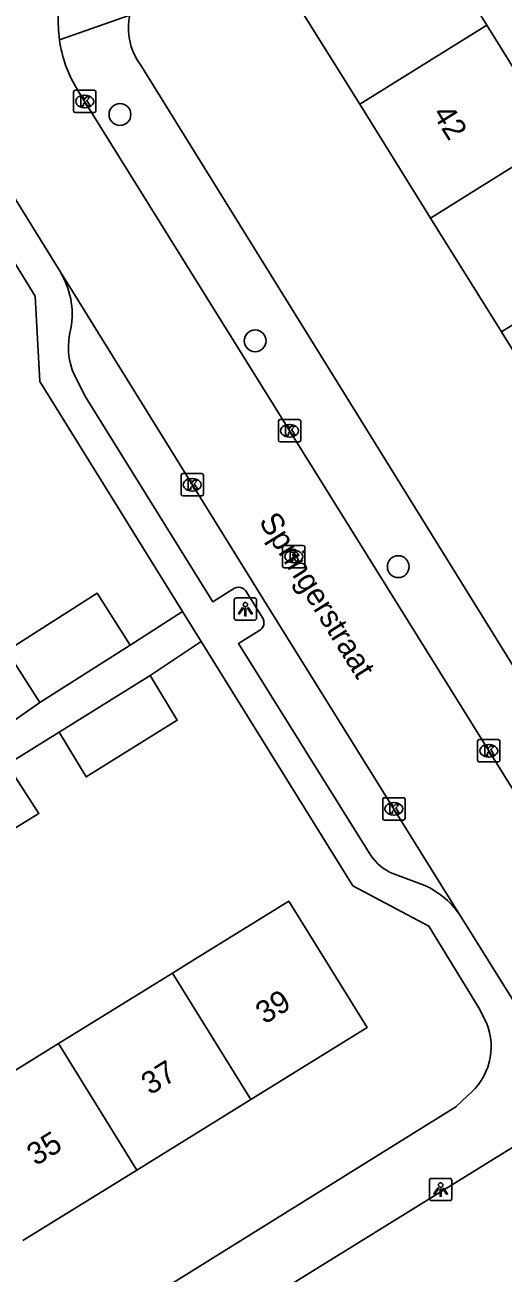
# Model space of a CAD drawing. Extents: x 160037 to 160839, y 385326 to 386441.
# Drawn here: x 160336.3 to 160357.7, y 386118.5 to 386174.4 of the extents above; entities that cross this region are included whole.
import ezdxf

# ---------------------------------------------------------------- set-up
doc = ezdxf.new("R2010")
doc.units = 0
for name, color, linetype in [('IMGEO_Boom', 7, 'Continuous'), ('IMGEO_Kolk', 7, 'Continuous'), ('IMGEO_Lichtpunt', 7, 'Continuous'), ('IMGEO_Openbare_ruimte_label', 7, 'Continuous'), ('IMGEO_Pand', 7, 'Continuous'), ('IMGEO_Pand_nummerreeks', 7, 'Continuous'), ('IMGEO_Rijbaan_lokaal_open', 7, 'Continuous'), ('IMGEO_Rioolput', 7, 'Continuous'), ('IMGEO_Voetpad_open', 7, 'Continuous')]:
    doc.layers.add(name, color=color, linetype=linetype)

msp = doc.modelspace()

# ---------------------------------------------------------------- linework, layer by layer
at = {"layer": 'IMGEO_Boom'}
for centre in [(160340.54, 386170.396), (160346.596, 386160.261), (160353.007, 386150.151)]:
    msp.add_circle(centre, 0.489, dxfattribs=at)
at = {"layer": 'IMGEO_Kolk'}
for p, q in [((160338.46, 386170.556), (160338.46, 386171.408)), ((160338.535, 386171.482), (160339.387, 386171.482)), ((160339.461, 386171.408), (160339.461, 386170.556)), ((160338.948, 386171.262), (160338.973, 386171.262)), ((160339.387, 386170.482), (160338.535, 386170.482)), ((160338.971, 386170.702), (160338.946, 386170.702)), ((160347.639, 386155.81), (160347.639, 386156.662)), ((160347.714, 386156.736), (160348.566, 386156.736)), ((160348.127, 386156.516), (160348.152, 386156.516)), ((160348.64, 386156.662), (160348.64, 386155.81)), ((160348.566, 386155.736), (160347.714, 386155.736)), ((160348.15, 386155.956), (160348.125, 386155.956)), ((160343.278, 386153.392), (160343.278, 386154.244)), ((160343.353, 386154.318), (160344.205, 386154.318)), ((160343.766, 386154.098), (160343.791, 386154.098)), ((160344.279, 386154.244), (160344.279, 386153.392)), ((160343.789, 386153.538), (160343.764, 386153.538)), ((160344.205, 386153.318), (160343.353, 386153.318)), ((160356.562, 386141.482), (160356.562, 386142.334)), ((160356.637, 386142.408), (160357.489, 386142.408)), ((160357.563, 386142.334), (160357.563, 386141.482)), ((160357.05, 386142.188), (160357.075, 386142.188)), ((160357.489, 386141.408), (160356.637, 386141.408)), ((160357.073, 386141.628), (160357.048, 386141.628)), ((160352.31, 386138.881), (160352.31, 386139.733)), ((160352.385, 386139.807), (160353.237, 386139.807)), ((160352.798, 386139.587), (160352.823, 386139.587)), ((160353.311, 386139.733), (160353.311, 386138.881)), ((160352.821, 386139.027), (160352.796, 386139.027)), ((160353.237, 386138.807), (160352.385, 386138.807))]:
    msp.add_line(p, q, dxfattribs=at)
for points in [[(160338.46, 386170.556), (160338.46, 386171.408)], [(160338.535, 386171.482), (160339.387, 386171.482)], [(160339.461, 386171.408), (160339.461, 386170.556)], [(160338.781, 386171.182), (160338.904, 386171.182), (160338.904, 386171.031), (160339.034, 386171.182), (160339.198, 386171.182), (160339.052, 386171.031), (160339.205, 386170.782), (160339.053, 386170.782), (160338.968, 386170.946), (160338.904, 386170.879), (160338.904, 386170.782), (160338.781, 386170.782), (160338.781, 386171.182)], [(160339.387, 386170.482), (160338.535, 386170.482)], [(160347.639, 386155.81), (160347.639, 386156.662)], [(160347.714, 386156.736), (160348.566, 386156.736)], [(160347.96, 386156.436), (160348.083, 386156.436), (160348.083, 386156.285), (160348.213, 386156.436), (160348.377, 386156.436), (160348.231, 386156.285), (160348.384, 386156.036), (160348.232, 386156.036), (160348.147, 386156.2), (160348.083, 386156.133), (160348.083, 386156.036), (160347.96, 386156.036), (160347.96, 386156.436)], [(160348.64, 386156.662), (160348.64, 386155.81)], [(160348.566, 386155.736), (160347.714, 386155.736)], [(160343.278, 386153.392), (160343.278, 386154.244)], [(160343.353, 386154.318), (160344.205, 386154.318)], [(160344.279, 386154.244), (160344.279, 386153.392)], [(160343.599, 386154.018), (160343.722, 386154.018), (160343.722, 386153.867), (160343.852, 386154.018), (160344.016, 386154.018), (160343.87, 386153.867), (160344.023, 386153.618), (160343.871, 386153.618), (160343.786, 386153.782), (160343.722, 386153.715), (160343.722, 386153.618), (160343.599, 386153.618), (160343.599, 386154.018)], [(160344.205, 386153.318), (160343.353, 386153.318)], [(160356.562, 386141.482), (160356.562, 386142.334)], [(160356.637, 386142.408), (160357.489, 386142.408)], [(160357.563, 386142.334), (160357.563, 386141.482)], [(160356.883, 386142.108), (160357.006, 386142.108), (160357.006, 386141.957), (160357.136, 386142.108), (160357.3, 386142.108), (160357.154, 386141.957), (160357.307, 386141.708), (160357.155, 386141.708), (160357.07, 386141.872), (160357.006, 386141.805), (160357.006, 386141.708), (160356.883, 386141.708), (160356.883, 386142.108)], [(160357.489, 386141.408), (160356.637, 386141.408)], [(160352.31, 386138.881), (160352.31, 386139.733)], [(160352.385, 386139.807), (160353.237, 386139.807)], [(160353.311, 386139.733), (160353.311, 386138.881)], [(160352.631, 386139.507), (160352.754, 386139.507), (160352.754, 386139.356), (160352.884, 386139.507), (160353.048, 386139.507), (160352.902, 386139.356), (160353.055, 386139.107), (160352.903, 386139.107), (160352.818, 386139.271), (160352.754, 386139.204), (160352.754, 386139.107), (160352.631, 386139.107), (160352.631, 386139.507)], [(160353.237, 386138.807), (160352.385, 386138.807)]]:
    msp.add_lwpolyline(points, dxfattribs=at)
for centre, start, end in [((160338.537, 386171.406), 91.552, 178.448), ((160338.537, 386171.406), 91.552, 178.448), ((160339.385, 386171.406), 1.552, 88.448), ((160339.385, 386171.406), 1.552, 88.448), ((160338.537, 386170.558), 181.552, 268.448), ((160338.537, 386170.558), 181.552, 268.448), ((160339.385, 386170.558), 271.552, 358.448), ((160339.385, 386170.558), 271.552, 358.448), ((160347.716, 386156.66), 91.552, 178.448), ((160347.716, 386156.66), 91.552, 178.448), ((160348.564, 386156.66), 1.552, 88.448), ((160348.564, 386156.66), 1.552, 88.448), ((160347.716, 386155.812), 181.552, 268.448), ((160347.716, 386155.812), 181.552, 268.448), ((160348.564, 386155.812), 271.552, 358.448), ((160348.564, 386155.812), 271.552, 358.448), ((160343.355, 386154.242), 91.552, 178.448), ((160343.355, 386154.242), 91.552, 178.448), ((160344.203, 386154.242), 1.552, 88.448), ((160344.203, 386154.242), 1.552, 88.448), ((160343.355, 386153.394), 181.552, 268.448), ((160343.355, 386153.394), 181.552, 268.448), ((160344.203, 386153.394), 271.552, 358.448), ((160344.203, 386153.394), 271.552, 358.448), ((160356.639, 386142.332), 91.552, 178.448), ((160356.639, 386142.332), 91.552, 178.448), ((160357.487, 386142.332), 1.552, 88.448), ((160357.487, 386142.332), 1.552, 88.448), ((160356.639, 386141.484), 181.552, 268.448), ((160356.639, 386141.484), 181.552, 268.448), ((160357.487, 386141.484), 271.552, 358.448), ((160357.487, 386141.484), 271.552, 358.448), ((160352.387, 386139.731), 91.552, 178.448), ((160352.387, 386139.731), 91.552, 178.448), ((160353.235, 386139.731), 1.552, 88.448), ((160353.235, 386139.731), 1.552, 88.448), ((160352.387, 386138.883), 181.552, 268.448), ((160352.387, 386138.883), 181.552, 268.448), ((160353.235, 386138.883), 271.552, 358.448), ((160353.235, 386138.883), 271.552, 358.448)]:
    msp.add_arc(centre, 0.0765, start, end, dxfattribs=at)
for centre, major_axis, ratio, start_param, end_param in [((160338.947, 386170.982), (-0.387, 0.002), 0.722429, 4.712389, 7.853982), ((160338.972, 386170.982), (-0.39, 0.002), 0.717154, 1.570796, 4.712389), ((160348.126, 386156.236), (-0.387, 0.002), 0.722429, 4.712389, 7.853982), ((160348.151, 386156.236), (-0.39, 0.002), 0.717154, 1.570796, 4.712389), ((160343.765, 386153.818), (-0.387, 0.002), 0.722429, 4.712389, 7.853982), ((160343.79, 386153.818), (-0.39, 0.002), 0.717154, 1.570796, 4.712389), ((160357.049, 386141.908), (-0.387, 0.002), 0.722429, 4.712389, 7.853982), ((160357.074, 386141.908), (-0.39, 0.002), 0.717154, 1.570796, 4.712389), ((160352.797, 386139.307), (-0.387, 0.002), 0.722429, 4.712389, 7.853982), ((160352.822, 386139.307), (-0.39, 0.002), 0.717154, 1.570796, 4.712389)]:
    msp.add_ellipse(centre, major_axis=major_axis, ratio=ratio, start_param=start_param, end_param=end_param, dxfattribs=at)
at = {"layer": 'IMGEO_Lichtpunt'}
for p, q in [((160345.661, 386148.655), (160345.661, 386147.848)), ((160345.661, 386148.655), (160345.661, 386147.848)), ((160346.563, 386148.75), (160345.755, 386148.75)), ((160346.563, 386148.75), (160345.755, 386148.75)), ((160346.657, 386147.848), (160346.657, 386148.655)), ((160346.657, 386147.848), (160346.657, 386148.655)), ((160345.755, 386147.754), (160346.563, 386147.754)), ((160345.755, 386147.754), (160346.563, 386147.754)), ((160355.309, 386122.761), (160354.501, 386122.761)), ((160355.309, 386122.761), (160354.501, 386122.761)), ((160354.407, 386122.666), (160354.407, 386121.859)), ((160354.407, 386122.666), (160354.407, 386121.859)), ((160355.403, 386121.859), (160355.403, 386122.666)), ((160355.403, 386121.859), (160355.403, 386122.666)), ((160354.501, 386121.765), (160355.309, 386121.765)), ((160354.501, 386121.765), (160355.309, 386121.765))]:
    msp.add_line(p, q, dxfattribs=at)
for points in [[(160346.035, 386148.319), (160346.074, 386148.291), (160345.886, 386148.029), (160345.848, 386148.056), (160346.035, 386148.319)], [(160346.137, 386148.271), (160346.184, 386148.271), (160346.184, 386147.949), (160346.137, 386147.949), (160346.137, 386148.271)], [(160346.247, 386148.291), (160346.285, 386148.318), (160346.472, 386148.056), (160346.433, 386148.028), (160346.247, 386148.291)], [(160354.781, 386122.33), (160354.82, 386122.302), (160354.632, 386122.04), (160354.594, 386122.067), (160354.781, 386122.33)], [(160354.883, 386122.282), (160354.93, 386122.282), (160354.93, 386121.96), (160354.883, 386121.96), (160354.883, 386122.282)], [(160354.993, 386122.302), (160355.031, 386122.329), (160355.218, 386122.067), (160355.179, 386122.039), (160354.993, 386122.302)]]:
    msp.add_lwpolyline(points, dxfattribs=at)
for centre in [(160346.16, 386148.453), (160354.906, 386122.464)]:
    msp.add_circle(centre, 0.0994, dxfattribs=at)
for centre, start, end in [((160345.755, 386148.655), 90, 180), ((160345.755, 386148.655), 90, 180), ((160346.563, 386148.655), 0, 90), ((160346.563, 386148.655), 0, 90), ((160345.755, 386147.848), 180, 270), ((160345.755, 386147.848), 180, 270), ((160346.563, 386147.848), 270, 0), ((160346.563, 386147.848), 270, 360), ((160354.501, 386122.666), 90, 180), ((160354.501, 386122.666), 90, 180), ((160355.309, 386122.666), 0, 90), ((160355.309, 386122.666), 0, 90), ((160354.501, 386121.859), 180, 270), ((160354.501, 386121.859), 180, 270), ((160355.309, 386121.859), 270, 0), ((160355.309, 386121.859), 270, 360)]:
    msp.add_arc(centre, 0.0946, start, end, dxfattribs=at)
at = {"layer": 'IMGEO_Pand'}
for points in [[(160356.97, 386174.4), (160353.721, 386179.618), (160348.03, 386176.074), (160351.279, 386170.856)], [(160351.279, 386170.856), (160356.97, 386174.4)], [(160360.144, 386169.303), (160356.97, 386174.4)], [(160351.279, 386170.856), (160354.453, 386165.759)], [(160360.144, 386169.303), (160354.453, 386165.759)], [(160354.453, 386165.759), (160357.628, 386160.661)], [(160357.628, 386160.661), (160363.319, 386164.205)], [(160357.628, 386160.661), (160360.802, 386155.563)], [(160336.951, 386144.064), (160335.473, 386146.382), (160339.517, 386148.959), (160340.994, 386146.641)], [(160340.994, 386146.641), (160336.951, 386144.064)], [(160337.811, 386142.735), (160341.891, 386145.277)], [(160337.811, 386142.735), (160339.025, 386140.734), (160343.104, 386143.276), (160341.891, 386145.277)], [(160332.927, 386136.669), (160336.901, 386139.096), (160335.492, 386141.288)], [(160342.892, 386131.955), (160343.853, 386132.55), (160348.104, 386135.18), (160351.609, 386129.515), (160346.397, 386126.29)], [(160337.79, 386128.799), (160342.892, 386131.955)], [(160346.397, 386126.29), (160342.892, 386131.955)], [(160332.687, 386125.641), (160337.79, 386128.799)], [(160337.79, 386128.799), (160341.295, 386123.133)], [(160346.397, 386126.29), (160341.295, 386123.133)], [(160341.295, 386123.133), (160336.192, 386119.976)]]:
    msp.add_lwpolyline(points, dxfattribs=at)
at = {"layer": 'IMGEO_Rijbaan_lokaal_open'}
for points in [[(160368.048, 386124.266), (160349.241, 386154.465), (160338.651, 386171.478)], [(160334.463, 386168.84), (160337.856, 386163.369)], [(160355.747, 386134.579), (160347.159, 386148.37), (160338.231, 386162.765), (160337.856, 386163.369)], [(160355.747, 386134.579), (160356.107, 386134.002), (160361.114, 386125.995)]]:
    msp.add_lwpolyline(points, dxfattribs=at)
for centre, radius, start, end in [((160343.623, 386174.571), 5.855, 121.88, 188.137), ((160343.63, 386174.575), 5.863, 188.1638, 211.8796)]:
    msp.add_arc(centre, radius, start, end, dxfattribs=at)
at = {"layer": 'IMGEO_Rioolput'}
for p, q in [((160347.827, 386150.178), (160347.827, 386151.03)), ((160347.902, 386151.104), (160348.754, 386151.104)), ((160348.315, 386150.884), (160348.34, 386150.884)), ((160348.828, 386151.03), (160348.828, 386150.178)), ((160348.338, 386150.324), (160348.313, 386150.324)), ((160348.754, 386150.104), (160347.902, 386150.104))]:
    msp.add_line(p, q, dxfattribs=at)
for points in [[(160347.827, 386150.178), (160347.827, 386151.03)], [(160347.902, 386151.104), (160348.754, 386151.104)], [(160348.416, 386150.802), (160348.164, 386150.804), (160348.164, 386150.404)], [(160348.342, 386150.723), (160348.288, 386150.723), (160348.288, 386150.642)], [(160348.828, 386151.03), (160348.828, 386150.178)], [(160348.164, 386150.404), (160348.288, 386150.404), (160348.288, 386150.566), (160348.299, 386150.566)], [(160348.288, 386150.642), (160348.34, 386150.642)], [(160348.346, 386150.537), (160348.417, 386150.404), (160348.557, 386150.404), (160348.492, 386150.53)], [(160348.754, 386150.104), (160347.902, 386150.104)]]:
    msp.add_lwpolyline(points, dxfattribs=at)
for centre, radius, start, end in [((160347.904, 386151.028), 0.0765, 91.552, 178.448), ((160347.904, 386151.028), 0.0765, 91.552, 178.448), ((160348.348, 386150.627), 0.0964, 77.0061, 93.1865), ((160348.362, 386150.684), 0.0378, 276.6634, 79.6772), ((160348.415, 386150.692), 0.109, 350.3612, 89.416), ((160348.752, 386151.028), 0.0765, 1.552, 88.448), ((160348.752, 386151.028), 0.0765, 1.552, 88.448), ((160347.904, 386150.18), 0.0765, 181.552, 268.448), ((160347.904, 386150.18), 0.0765, 181.552, 268.448), ((160348.298, 386150.513), 0.0533, 26.0293, 88.6989), ((160348.324, 386150.831), 0.19, 274.7715, 282.9687), ((160348.413, 386150.692), 0.112, 277.5842, 350.9817), ((160348.397, 386150.477), 0.108, 29.5134, 73.7905), ((160348.752, 386150.18), 0.0765, 271.552, 358.448), ((160348.752, 386150.18), 0.0765, 271.552, 358.448)]:
    msp.add_arc(centre, radius, start, end, dxfattribs=at)
for centre, major_axis, ratio, start_param, end_param in [((160348.314, 386150.604), (-0.387, 0.002), 0.722429, 4.712389, 7.853982), ((160348.339, 386150.604), (-0.39, 0.002), 0.717154, 1.570796, 4.712389)]:
    msp.add_ellipse(centre, major_axis=major_axis, ratio=ratio, start_param=start_param, end_param=end_param, dxfattribs=at)
at = {"layer": 'IMGEO_Voetpad_open'}
for points in [[(160340.977, 386174.852), (160337.826, 386173.742)], [(160376.697, 386115.797), (160341.444, 386172.646)], [(160343.347, 386148.141), (160336.954, 386158.446), (160336.745, 386162.264), (160333.355, 386167.748)], [(160338.504, 386158.72), (160339.001, 386157.761), (160344.695, 386148.581), (160345.6, 386149.144)], [(160346.22, 386149), (160346.906, 386147.896)], [(160343.347, 386148.141), (160340.994, 386146.641)], [(160344.179, 386146.799), (160343.347, 386148.141)], [(160341.891, 386145.277), (160344.179, 386146.799)], [(160356.957, 386129.732), (160356.619, 386130.39), (160354.382, 386134.055), (160350.965, 386135.86), (160344.179, 386146.799)], [(160346.762, 386147.276), (160345.856, 386146.712), (160351.779, 386137.216), (160351.782, 386137.212)], [(160336.951, 386144.064), (160334.981, 386142.691)], [(160335.492, 386141.288), (160337.811, 386142.735)], [(160352.769, 386136.411), (160354.079, 386135.926)], [(160306.39, 386097.366), (160312.51, 386101.101), (160313.388, 386099.731), (160355.583, 386125.97), (160356.119, 386126.467)], [(160361.114, 386125.995), (160346.775, 386117.126), (160339.026, 386112.29), (160343.284, 386105.352)]]:
    msp.add_lwpolyline(points, dxfattribs=at)
for centre, radius, start, end in [((160343.675, 386174.271), 2.76, 167.8455, 216.0601), ((160334.707, 386161.445), 3.69, 350.1807, 31.4189), ((160341.279, 386159.987), 3.051, 164.2393, 204.5456), ((160345.851, 386148.819), 0.411, 26.1938, 127.655), ((160346.581, 386147.645), 0.411, 296.1938, 37.655), ((160353.613, 386138.459), 2.215, 214.2675, 247.6103), ((160352.653, 386132.454), 3.754, 34.4839, 67.6706), ((160354.359, 386128.659), 2.811, 308.7585, 22.4517)]:
    msp.add_arc(centre, radius, start, end, dxfattribs=at)

# ---------------------------------------------------------------- texts
at = {"layer": 'IMGEO_Openbare_ruimte_label'}
msp.add_text('Springerstraat', height=1, rotation=301.9568, dxfattribs=at).set_placement((160346.737, 386152.184))
at = {"layer": 'IMGEO_Pand_nummerreeks'}
for s, rotation, p in [('42', 301.9103, (160354.512, 386170.432)), ('39', 31.746, (160347.018, 386129.638)), ('37', 31.746, (160341.893, 386126.467)), ('35', 31.746, (160336.769, 386123.296))]:
    msp.add_text(s, height=1, rotation=rotation, dxfattribs=at).set_placement(p)

doc.saveas('drawing.dxf')
